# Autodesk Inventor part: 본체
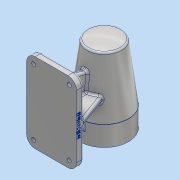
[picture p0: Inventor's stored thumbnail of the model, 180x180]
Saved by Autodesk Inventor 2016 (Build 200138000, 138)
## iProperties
Created: 2018-09
Part Number: 본체
Material: 알루미늄 6061
Document SubType Name: Sheet Metal
Designer: 605-07
Density: 2.7 g/cm^3
Sheet Metal Rule: 기본값_mm
Appearance: 알루미늄 - 평지
Mass: 735.105 g
Surface Area: 661.48 cm^2
Volume: 272.261 cm^3
Author: 605-07
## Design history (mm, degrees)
sketch "스케치1"
  geometry: C1 r 34 at (0, 0); 1 further point
  constraints: 1 centre point, 1 coincident
  dimensions: "d0" = 68 diameter of C1
extrude "돌출1" new body sketch "스케치1" distance "d1" = 28; taper "d2" = 0 deg
sketch "스케치2"
  geometry: L1 (34, 28)-(-34, 28) reference; L2 (34, 0)-(34, 28) reference; L3 (34, 28)-(24.144, 108.27); L4 (0, 112)-(0, 28); A1 r 80 centre (0, 32) between (24.144, 108.27) and (0, 112); 1 further point
  constraints: 4 end point, 2 point on circle, 1 centre point, 1 midpoint, 1 vertical alignment
  dimensions: "d4" = 7 deg angle of L2 L3; "d5" = 160 diameter of A1; "d6" = 112 vertical distance of L2.start L4.start; "d7" = 84 distance of L4.start L4.end
revolve "회전1" sketch "스케치2" stored, may be unused: angle "d8" = 90 deg
fillet "모깎기1" dims "d9" = 3
sketch "스케치3"
  geometry: L1 (0, 18)-(-64, 18); L2 (-64, 18)-(-64, 94); L3 (-64, 94)-(0, 76.851); L4 (0, 76.851)-(0, 18); A1 r 80 centre (0, 32) between (22.238, 108.847) and (-22.238, 108.847) reference; 3 further points
  constraints: 8 end point, 1 horizontal, 1 midpoint, 1 parallel, 1 perpendicular, 1 point on circle, 1 vertical alignment
  dimensions: "d10" = 64 distance between parallel lines of L2 L4; "d11" = 18 distance from line of point (0, 0) L1; "d12" = 18 vertical distance of L2.end point (0, 112); "d13" = 75 deg angle of L2 L3
extrude "돌출2" join sketch "스케치3" stored distance "d14" = 8; taper "d15" = 0 deg
node "작업 평면1"
sketch "스케치4"
  geometry: L1 (11.706, 0)-(35, -64); L2 (4, -26.823)-(4, -64) reference; L3 (11.706, 0)-(0, 0); L4 (0, 0)-(0, -64); L5 (4, -64)-(-4, -64) reference; L6 (35, -64)-(0, -64)
  constraints: 8 end point, 1 horizontal, 1 midpoint, 1 perpendicular
  dimensions: "d17" = 70 deg angle of L1 L6; "d18" = 35 distance of L1.end L4.end
extrude "돌출3" join sketch "스케치4" stored distance "d19" = 8; taper "d20" = 0 deg
sketch "스케치5"
  geometry: L1 (39, -18)-(-31, -18); L2 (-31, -18)-(-31, 94); L3 (-31, 94)-(39, 94); L4 (39, 94)-(39, -18); L5 (0, 0)-(0, 34) reference; L6 (8, 0)-(0, 0) reference; L7 (8, 34)-(8, 0) reference; L8 (39, 34)-(8, 34) reference; L9 (39, 42)-(39, 34) reference; L10 (8, 42)-(39, 42) reference; L11 (8, 76)-(8, 42) reference; L12 (8, 76)-(0, 76) reference; L13 (0, 42)-(0, 76) reference; L14 (0, 42)-(-31, 42) reference; L15 (-31, 42)-(-31, 34) reference; L16 (-31, 34)-(0, 34) reference; 2 further points
  constraints: 8 end point, 2 parallel, 1 horizontal, 1 perpendicular
  dimensions: "d21" = 112 distance of L1.end L2.end; "d22" = 70 distance of L1.start L1.end; "d23" = 56 distance from line of L3 point (4, 38); "d24" = 4 horizontal distance of L13.start point (4, 38); "d25" = 4 distance from line of point (4, 38) L10; "d26" = 35 distance from line of L2 point (4, 38)
extrude "돌출4" join sketch "스케치5" distance "d27" = 10; taper "d28" = 0 deg
fillet "모깎기2" dims "d29" = 12
sketch "스케치6"
  geometry: L1 (39, 6)-(39, -82) reference; L2 (-31, -82)-(-31, 6) reference; L3 (-19, 18)-(27, 18) reference; 3 further points
  dimensions: "d31" = 10 distance from line of L1 point (29, 8); "d32" = 10 distance from line of point (-21, 8) L2; "d33" = 10 distance from line of L3 point (-21, 8); "d34" = 10 distance from line of L3 point (29, 8)
hole "구멍1" sketch "스케치6" at (29, 8), (-21, 8) diameter "d35" = 5.5; stored, may be unused: countersink angle "d39" = 90 deg, drill point angle "d41" = 118 deg; dims "d36" = 6, "d37" = 9.5, "d38" = 5.4, "d40" = 0.5 (derived)
sketch "스케치7"
  geometry: C1 r 21 at (0, 0); 1 further point
  constraints: 1 centre point, 1 coincident
  dimensions: "d42" = 42 diameter of C1
extrude "돌출5" cut sketch "스케치7" distance "d43" = 15; taper "d44" = 0 deg
sketch "스케치8"
  geometry: C1 r 24 at (0, 0); 1 further point
  constraints: 1 centre point, 1 coincident
  dimensions: "d45" = 48 diameter of C1
extrude "돌출6" cut sketch "스케치8" distance "d46" = 54; taper "d47" = 0 deg
sketch "스케치9"
  geometry: C1 r 21 at (0, 0); 1 further point
  constraints: 1 centre point, 1 coincident
  dimensions: "d48" = 42 diameter of C1
extrude "돌출7" cut sketch "스케치9" distance "d49" = 12; taper "d50" = 0 deg
sketch "스케치10"
  geometry: C1 r 17.5 at (0, 0); 1 further point
  constraints: 1 centre point, 1 coincident
  dimensions: "d51" = 35 diameter of C1
extrude "돌출8" cut sketch "스케치10" distance "d52" = 18; taper "d53" = 0 deg
sketch "스케치11"
  geometry: C1 r 16 at (0, 0); 1 further point
  constraints: 1 centre point, 1 coincident
  dimensions: "d54" = 32 diameter of C1
extrude "돌출9" cut sketch "스케치11" distance "d55" = 4; taper "d56" = 0 deg
sketch "스케치12"
  geometry: C1 r 10.5 at (0, 0); 1 further point
  constraints: 1 centre point, 1 coincident
  dimensions: "d57" = 21 diameter of C1
extrude "돌출10" cut sketch "스케치12" distance "d58" = 3; taper "d59" = 0 deg
fillet "모깎기3" dims "d60" = 3
fillet "모깎기4" dims "d61" = 0.3
fillet "모깎기5" dims "d62" = 3
fillet "모깎기6" dims "d63" = 3
chamfer "모따기1" distance "d64" = 1; stored, may be unused: second distance "d65" = 2, angle "d66" = 45 deg
sketch "스케치13"
  geometry: 2 further points
  constraints: 1 vertical alignment
  dimensions: "d67" = 26 distance of point (0, 0) point (0, 26)
hole "구멍2" sketch "스케치13" at (0, 26) diameter "d68" = 3.242; stored, may be unused: countersink angle "d72" = 90 deg, drill point angle "d74" = 118 deg; dims "d69" = 8, "d70" = 9.5, "d71" = 5.4, "d73" = 11
fillet "모깎기7" dims "d75" = 3
fillet "모깎기8" dims "d76" = 3
fillet "모깎기9" dims "d77" = 3
fillet "모깎기10" dims "d78" = 3
fillet "모깎기11" dims "d79" = 3
fillet "모깎기12" dims "d80" = 3
fillet "모깎기13" dims "d81" = 3
fillet "모깎기14" dims "d82" = 3
fillet "모깎기15" dims "d83" = 3
fillet "모깎기16" dims "d84" = 3
fillet "모깎기17" dims "d85" = 3
fillet "모깎기18" dims "d86" = 3
fillet "모깎기19" dims "d87" = 3
fillet "모깎기20" dims "d88" = 3
fillet "모깎기21" dims "d89" = 3
fillet "모깎기22" dims "d90" = 3
fillet "모깎기23" dims "d91" = 3
fillet "모깎기24" dims "d92" = 3
fillet "모깎기25" dims "d93" = 3
sketch "스케치14"
  geometry: L1 (27.408, 5.402)-(60.592, 5.402); L2 (60.592, 5.402)-(60.592, 0.598); L3 (60.592, 0.598)-(27.408, 0.598); L4 (27.408, 0.598)-(27.408, 5.402); L5 (27.408, 3)-(60.592, 3); L6 (44, 5.402)-(44, 0.598); L7 (100, 0)-(100, 7) reference; L8 (100, 0)-(88, 0) reference; 1 further point
  constraints: 4 end point, 4 midpoint, 2 other
  dimensions: "d94" = 56 distance between parallel lines of L7 L6; "d95" = 3 distance between parallel lines of L8 L5
feature "엠보싱1" sketch "스케치14" dims "d96" = 0.5, "d97" = 0
node "솔리드1"
mirror "대칭1"
mirror "대칭2"
pattern_circular "원형 패턴1" dims angle "d99" = 360 deg
node "투영된 루프1"
other parameters: "BendRadius" = 0.5 (derived), "BendReliefWidth" = 0.5 (derived), "BendReliefDepth" = 0.25 (derived), "CornerReliefSize" = 2 (derived), "SeamGap" = 0.01, "MinimumRemnant" = 1 (derived), "TransitionRadius" = 0.5 (= BendRadius), "d16" = 56
